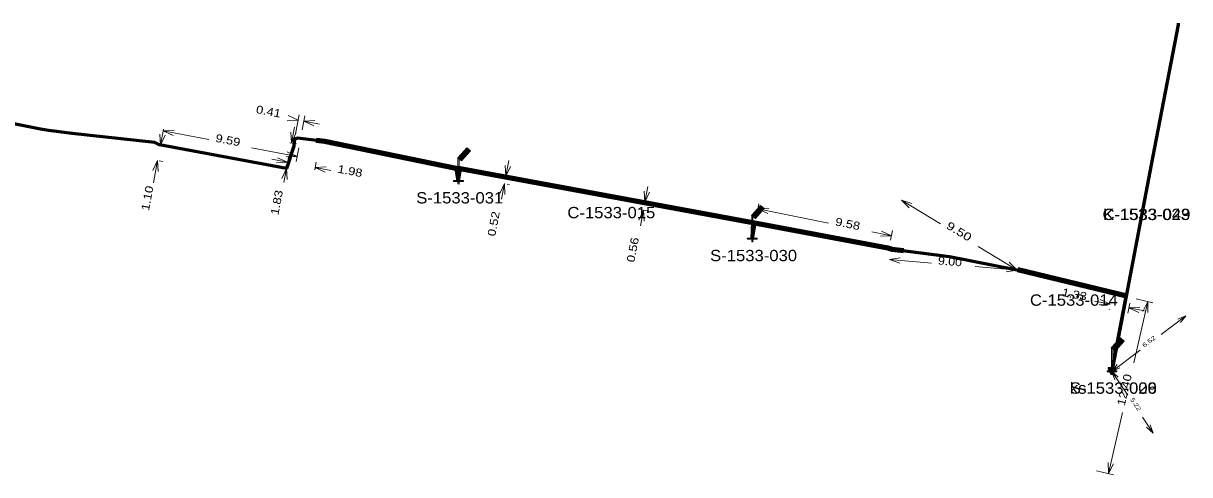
# Model space of a CAD drawing. Extents: x -600908 to -600738, y -1162522 to -1162430.
# Drawn here: x -600820.3 to -600738.3, y -1162522.3 to -1162490.6 of the extents above; entities that cross this region are included whole.
import ezdxf
from ezdxf.enums import TextEntityAlignment as Align

# ---------------------------------------------------------------- set-up
doc = ezdxf.new("R2010")
doc.units = 0
doc.header["$LTSCALE"] = 0.23
for name, color, linetype, lineweight in [('10', 7, 'Continuous', 13), ('11', 7, 'Continuous', 60), ('5', 7, 'Continuous', 13), ('6', 7, 'Continuous', 25), ('60', 7, 'Continuous', 13)]:
    doc.layers.add(name, color=color, linetype=linetype, lineweight=lineweight)

msp = doc.modelspace()

# ---------------------------------------------------------------- hatches: boundary and pattern name
at = {"layer": '10'}
for points in [[(-600743.996, -1162514.778), (-600743.996, -1162514.84), (-600743.809, -1162515.278), (-600743.683, -1162515.278), (-600743.496, -1162514.84), (-600743.496, -1162514.778)], [(-600743.809, -1162515.153), (-600743.809, -1162514.84), (-600743.621, -1162514.84), (-600743.621, -1162514.903), (-600743.746, -1162514.903), (-600743.746, -1162514.965), (-600743.683, -1162514.965), (-600743.683, -1162515.028), (-600743.746, -1162515.028), (-600743.746, -1162515.153)]]:
    msp.add_hatch(color=256, dxfattribs=at).paths.add_polyline_path(points)
at = {"layer": '5'}
for points in [[(-600789.098, -1162499.309), (-600788.839, -1162499.54), (-600789.469, -1162500.24), (-600789.735, -1162500.016)], [(-600790.036, -1162501.626), (-600789.336, -1162501.626), (-600789.336, -1162501.689), (-600790.029, -1162501.689)], [(-600768.438, -1162503.369), (-600768.179, -1162503.6), (-600768.809, -1162504.3), (-600769.075, -1162504.076)], [(-600769.376, -1162505.686), (-600768.676, -1162505.686), (-600768.676, -1162505.749), (-600769.369, -1162505.749)], [(-600743.147, -1162512.691), (-600742.888, -1162512.922), (-600743.518, -1162513.622), (-600743.784, -1162513.398)], [(-600744.085, -1162515.008), (-600743.385, -1162515.008), (-600743.385, -1162515.071), (-600744.078, -1162515.071)]]:
    msp.add_hatch(color=256, dxfattribs=at).paths.add_polyline_path(points)

# ---------------------------------------------------------------- linework, layer by layer
at = {"layer": '10'}
for points in [[(-600743.996, -1162514.778), (-600743.996, -1162514.84), (-600743.809, -1162515.278), (-600743.683, -1162515.278), (-600743.496, -1162514.84), (-600743.496, -1162514.778)], [(-600743.809, -1162515.153), (-600743.809, -1162514.84), (-600743.621, -1162514.84), (-600743.621, -1162514.903), (-600743.746, -1162514.903), (-600743.746, -1162514.965), (-600743.683, -1162514.965), (-600743.683, -1162515.028), (-600743.746, -1162515.028), (-600743.746, -1162515.153)]]:
    msp.add_lwpolyline(points, close=True, dxfattribs=at)
at = {"layer": '11', "lineweight": 90}
msp.add_line((-600742.691, -1162509.758), (-600750.348, -1162507.91), dxfattribs=at)
at = {"layer": '11'}
for points in [[(-600739.08, -1162490.56), (-600739.09, -1162490.67), (-600740.877, -1162500.018), (-600743.75, -1162515.05)], [(-600743.75, -1162515.05), (-600742.736, -1162509.787), (-600750.41, -1162507.92), (-600755.16, -1162506.98), (-600759.2, -1162506.47), (-600759.5, -1162506.37), (-600768.835, -1162504.605), (-600769.04, -1162505.7), (-600768.981, -1162504.589), (-600789.552, -1162500.804), (-600789.7, -1162501.64), (-600789.854, -1162500.77), (-600799.08, -1162498.87), (-600800.98, -1162498.65), (-600801.2, -1162498.7), (-600801.25, -1162499.2), (-600801.78, -1162500.78), (-600810.7, -1162499.11), (-600811.04, -1162498.94), (-600816.85, -1162498.32), (-600818.51, -1162498.11), (-600819.06, -1162498.01), (-600833.12, -1162495.19)]]:
    msp.add_lwpolyline(points, dxfattribs=at)
at = {"layer": '11', "lineweight": 90}
msp.add_lwpolyline([(-600758.4, -1162506.557), (-600759.2, -1162506.47), (-600759.5, -1162506.37), (-600768.981, -1162504.589), (-600789.552, -1162500.804), (-600789.854, -1162500.77), (-600799.08, -1162498.87), (-600799.685, -1162498.801)], dxfattribs=at)
at = {"layer": '5'}
for points in [[(-600789.098, -1162499.309), (-600788.839, -1162499.54), (-600789.469, -1162500.24), (-600789.735, -1162500.016)], [(-600789.721, -1162500.016), (-600789.637, -1162500.023), (-600789.637, -1162501.871), (-600789.721, -1162501.864)], [(-600790.036, -1162501.626), (-600789.336, -1162501.626), (-600789.336, -1162501.689), (-600790.029, -1162501.689)], [(-600768.438, -1162503.369), (-600768.179, -1162503.6), (-600768.809, -1162504.3), (-600769.075, -1162504.076)], [(-600769.061, -1162504.076), (-600768.977, -1162504.083), (-600768.977, -1162505.931), (-600769.061, -1162505.924)], [(-600769.376, -1162505.686), (-600768.676, -1162505.686), (-600768.676, -1162505.749), (-600769.369, -1162505.749)], [(-600743.147, -1162512.691), (-600742.888, -1162512.922), (-600743.518, -1162513.622), (-600743.784, -1162513.398)], [(-600743.77, -1162513.398), (-600743.686, -1162513.405), (-600743.686, -1162515.253), (-600743.77, -1162515.246)], [(-600744.085, -1162515.008), (-600743.385, -1162515.008), (-600743.385, -1162515.071), (-600744.078, -1162515.071)]]:
    msp.add_lwpolyline(points, close=True, dxfattribs=at)
at = {"layer": '6'}
for points in [[(-600739.08, -1162490.56), (-600739.09, -1162490.67), (-600740.877, -1162500.018), (-600743.75, -1162515.05)], [(-600743.75, -1162515.05), (-600742.736, -1162509.787), (-600750.41, -1162507.92), (-600755.16, -1162506.98), (-600759.2, -1162506.47), (-600759.5, -1162506.37), (-600768.835, -1162504.605), (-600769.04, -1162505.7), (-600768.981, -1162504.589), (-600789.552, -1162500.804), (-600789.7, -1162501.64), (-600789.854, -1162500.77), (-600799.08, -1162498.87), (-600800.98, -1162498.65), (-600801.2, -1162498.7), (-600801.25, -1162499.2), (-600801.78, -1162500.78), (-600810.7, -1162499.11), (-600811.04, -1162498.94), (-600816.85, -1162498.32), (-600818.51, -1162498.11), (-600819.06, -1162498.01), (-600833.12, -1162495.19)]]:
    msp.add_lwpolyline(points, dxfattribs=at)
at = {"layer": '60'}
for p, q in [((-600801.13, -1162498.332), (-600800.878, -1162497.004)), ((-600800.665, -1162498.064), (-600800.479, -1162497.08)), ((-600799.443, -1162497.658), (-600800.548, -1162497.449)), ((-600810.421, -1162498.018), (-600810.631, -1162499.123)), ((-600807.233, -1162498.742), (-600810.443, -1162498.133)), ((-600801.22, -1162497.875), (-600801.433, -1162498.979)), ((-600810.491, -1162498.386), (-600810.513, -1162498.501)), ((-600801.545, -1162498.958), (-600801.065, -1162499.05)), ((-600810.332, -1162499.18), (-600810.262, -1162499.193)), ((-600804.227, -1162499.312), (-600801.017, -1162499.921)), ((-600800.905, -1162499.329), (-600801.087, -1162500.289)), ((-600811.134, -1162501.778), (-600810.836, -1162500.205)), ((-600810.73, -1162500.225), (-600810.467, -1162500.274)), ((-600802.802, -1162500.128), (-600801.696, -1162500.336)), ((-600801.711, -1162500.411), (-600801.627, -1162499.968)), ((-600799.786, -1162500.87), (-600799.684, -1162500.334)), ((-600798.648, -1162500.911), (-600799.754, -1162500.702)), ((-600786.151, -1162500.22), (-600786.361, -1162501.325)), ((-600801.968, -1162501.759), (-600801.78, -1162500.78)), ((-600801.412, -1162500.851), (-600801.411, -1162500.851)), ((-600786.72, -1162501.257), (-600786.729, -1162501.255)), ((-600786.667, -1162502.937), (-600786.457, -1162501.832)), ((-600786.263, -1162501.869), (-600786.089, -1162501.902)), ((-600776.362, -1162502.047), (-600776.573, -1162503.152)), ((-600776.93, -1162503.084), (-600776.941, -1162503.082)), ((-600755.796, -1162504.661), (-600758.54, -1162503)), ((-600776.929, -1162503.65), (-600776.309, -1162503.769)), ((-600776.888, -1162504.803), (-600776.677, -1162503.698)), ((-600768.761, -1162504.237), (-600768.562, -1162503.249)), ((-600763.659, -1162504.617), (-600768.636, -1162503.616)), ((-600760.626, -1162505.227), (-600759.247, -1162505.504)), ((-600759.311, -1162505.821), (-600759.173, -1162505.136)), ((-600753.154, -1162506.259), (-600750.41, -1162507.92)), ((-600756.431, -1162507.423), (-600759.38, -1162507.18)), ((-600753.359, -1162507.677), (-600750.41, -1162507.92)), ((-600744.961, -1162510.114), (-600743.856, -1162510.325)), ((-600742.48, -1162510.238), (-600742.615, -1162510.943)), ((-600741.439, -1162510.785), (-600742.544, -1162510.575)), ((-600742.206, -1162514.441), (-600741.221, -1162510.142)), ((-600742.044, -1162509.954), (-600740.855, -1162510.226)), ((-600743.921, -1162510.668), (-600743.926, -1162510.693)), ((-600740.286, -1162512.443), (-600738.54, -1162511.13)), ((-600741.764, -1162513.556), (-600743.75, -1162515.05)), ((-600742.633, -1162516.722), (-600743.75, -1162515.05)), ((-600743.006, -1162517.934), (-600743.991, -1162522.232)), ((-600741.594, -1162518.276), (-600740.85, -1162519.39)), ((-600744.814, -1162522.044), (-600743.625, -1162522.316))]:
    msp.add_line(p, q, dxfattribs=at)
for points in [[(-600801.65, -1162497.049), (-600800.948, -1162497.373), (-600801.72, -1162497.417)], [(-600799.847, -1162497.773), (-600800.548, -1162497.449), (-600799.777, -1162497.404)], [(-600809.741, -1162498.457), (-600810.443, -1162498.133), (-600809.671, -1162498.088)], [(-600801.107, -1162498.278), (-600801.433, -1162498.979), (-600801.475, -1162498.208)], [(-600810.307, -1162498.421), (-600810.631, -1162499.123), (-600810.675, -1162498.351)], [(-600801.719, -1162499.597), (-600801.017, -1162499.921), (-600801.789, -1162499.965)], [(-600811.159, -1162500.907), (-600810.836, -1162500.205), (-600810.791, -1162500.976)], [(-600802.399, -1162500.013), (-600801.696, -1162500.336), (-600802.468, -1162500.382)], [(-600799.052, -1162501.026), (-600799.754, -1162500.702), (-600798.982, -1162500.657)], [(-600786.036, -1162500.624), (-600786.361, -1162501.325), (-600786.405, -1162500.554)], [(-600802.105, -1162501.481), (-600801.78, -1162500.78), (-600801.737, -1162501.552)], [(-600786.781, -1162502.534), (-600786.457, -1162501.832), (-600786.413, -1162502.604)], [(-600776.248, -1162502.45), (-600776.573, -1162503.152), (-600776.616, -1162502.38)], [(-600757.995, -1162503.549), (-600758.54, -1162503), (-600757.801, -1162503.228)], [(-600777.002, -1162504.4), (-600776.677, -1162503.698), (-600776.634, -1162504.47)], [(-600767.938, -1162503.948), (-600768.636, -1162503.616), (-600767.864, -1162503.58)], [(-600759.946, -1162505.172), (-600759.247, -1162505.504), (-600760.019, -1162505.54)], [(-600758.648, -1162507.429), (-600759.38, -1162507.18), (-600758.617, -1162507.055)], [(-600751.142, -1162507.671), (-600750.41, -1162507.92), (-600751.173, -1162508.045)], [(-600750.955, -1162507.371), (-600750.41, -1162507.92), (-600751.149, -1162507.692)], [(-600744.557, -1162510), (-600743.856, -1162510.325), (-600744.628, -1162510.368)], [(-600741.843, -1162510.899), (-600742.544, -1162510.575), (-600741.772, -1162510.531)], [(-600741.571, -1162510.832), (-600741.221, -1162510.142), (-600741.206, -1162510.915)], [(-600739.11, -1162511.371), (-600738.54, -1162511.13), (-600738.929, -1162511.611)], [(-600743.18, -1162514.809), (-600743.75, -1162515.05), (-600743.361, -1162514.569)], [(-600743.541, -1162515.632), (-600743.75, -1162515.05), (-600743.292, -1162515.466)], [(-600741.059, -1162518.808), (-600740.85, -1162519.39), (-600741.308, -1162518.974)], [(-600743.641, -1162521.543), (-600743.991, -1162522.232), (-600744.006, -1162521.46)]]:
    msp.add_lwpolyline(points, dxfattribs=at)

# ---------------------------------------------------------------- texts
at = {"layer": '10', "width": 1.1}
msp.add_text('ks1533-006', height=0.7955, dxfattribs=at).set_placement((-600743.64, -1162516.623), align=Align.CENTER)
at = {"layer": '11', "width": 1.1}
for s, p in [('C-1533-015', (-600778.936, -1162504.274)), ('C-1533-049', (-600741.309, -1162504.4)), ('C-1533-014', (-600746.414, -1162510.429))]:
    msp.add_text(s, height=0.7955, dxfattribs=at).set_placement(p, align=Align.CENTER)
at = {"layer": '5', "width": 1.1}
for s, p in [('S-1533-031', (-600789.594, -1162503.235)), ('S-1533-030', (-600768.934, -1162507.295)), ('S-1533-029', (-600743.643, -1162516.617))]:
    msp.add_text(s, height=0.7955, dxfattribs=at).set_placement(p, align=Align.CENTER)
at = {"layer": '6', "width": 1.1}
msp.add_text('K-1533-023', height=0.7955, dxfattribs=at).set_placement((-600741.309, -1162504.4), align=Align.CENTER)
at = {"layer": '60'}
for s, height, rotation, width, p in [('0.41', 0.5625, 349.257, 1.2, (-600803.951, -1162496.87)), ('9.59', 0.5625, 349.257, 1.2, (-600806.803, -1162498.89)), ('1.98', 0.5625, 349.327, 1.2, (-600798.218, -1162501.059)), ('1.10', 0.5625, 79.276, 1.2, (-600811.446, -1162503.779)), ('1.83', 0.5625, 79.102, 1.2, (-600802.349, -1162504.084)), ('0.52', 0.5625, 79.233, 1.2, (-600787.102, -1162505.577)), ('9.58', 0.5625, 348.635, 1.2, (-600763.232, -1162504.769)), ('9.50', 0.5625, 328.819, 1.3, (-600755.445, -1162504.949)), ('0.56', 0.5625, 79.185, 1.2, (-600777.319, -1162507.407)), ('9.00', 0.5625, 355.284, 1.15, (-600755.988, -1162507.526)), ('1.33', 0.5625, 349.208, 1.2, (-600747.286, -1162509.737)), ('6.52', 0.3, 36.958, 1.35, (-600741.471, -1162513.379)), ('12.40', 0.5625, 77.095, 1.2, (-600742.842, -1162517.511)), ('5.22', 0.3, 303.751, 1.3, (-600742.473, -1162517.025))]:
    msp.add_text(s, height=height, rotation=rotation, dxfattribs=dict(at, width=width)).set_placement(p)

doc.saveas('drawing.dxf')
